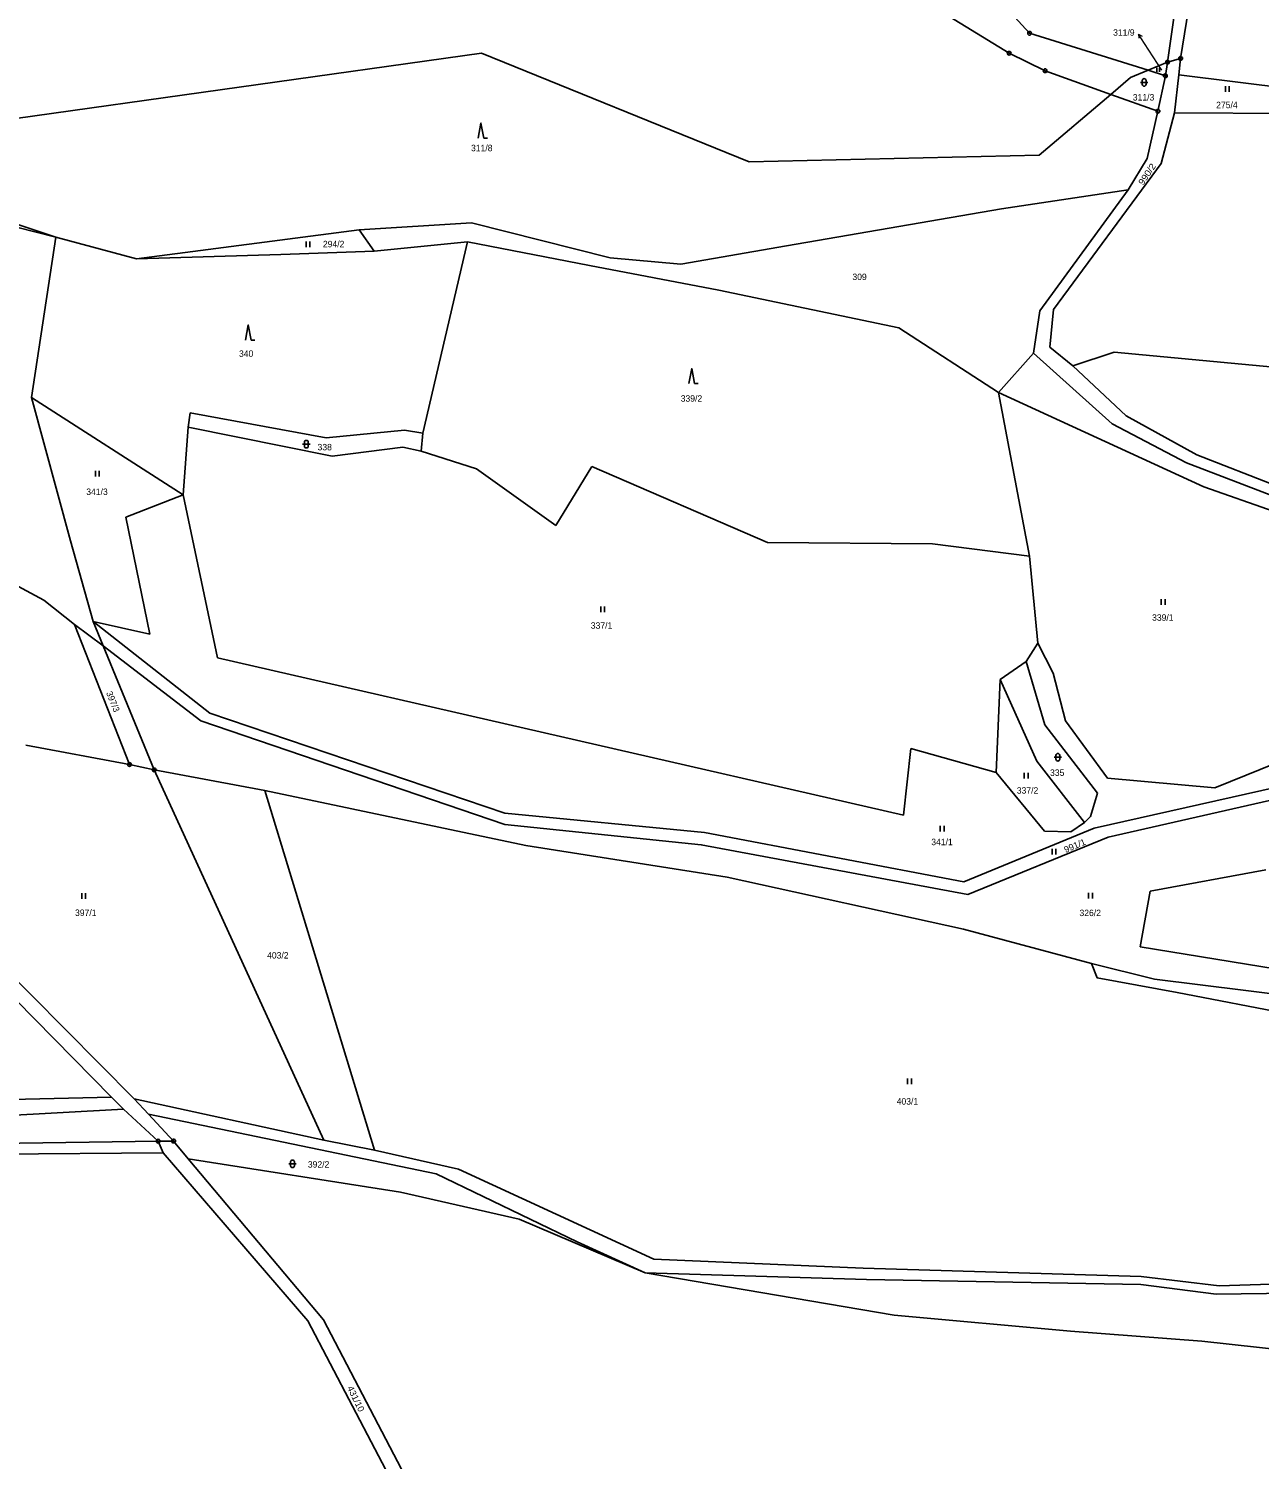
# Model space of a CAD drawing. Extents: x -754970 to -752637, y -970569 to -968179.
# Drawn here: x -753959.6 to -753633.5, y -968975.7 to -968596.7 of the extents above; entities that cross this region are included whole.
import ezdxf
from ezdxf.enums import TextEntityAlignment as Align

# ---------------------------------------------------------------- set-up
doc = ezdxf.new("R2010")
doc.units = 0
doc.header["$LTSCALE"] = 0.68
for name, color, linetype, lineweight in [('1', 7, 'Continuous', 25), ('3', 7, 'Continuous', 25), ('7', 7, 'Continuous', 13), ('8', 7, 'Continuous', 25)]:
    doc.layers.add(name, color=color, linetype=linetype, lineweight=lineweight)
doc.layers.add('2', color=7, linetype='Continuous')

msp = doc.modelspace()

# ---------------------------------------------------------------- linework, layer by layer
at = {"layer": '1'}
for p, q in [((-753718.31, -968571.75), (-753694.38, -968597.91)), ((-753657.81, -968605.58), (-753653.38, -968573.68)), ((-753650, -968577.63), (-753654.36, -968604.55)), ((-753725.93, -968587.15), (-753699.79, -968603.19)), ((-753662.97, -968607.71), (-753694.38, -968597.91)), ((-754013.82, -968627.61), (-753839.61, -968603.2)), ((-753839.61, -968603.2), (-753768.69, -968632)), ((-753699.79, -968603.19), (-753690.27, -968607.83)), ((-753672.85, -968614.08), (-753690.27, -968607.83)), ((-753662.97, -968607.71), (-753667.6, -968609.62)), ((-753657.81, -968605.58), (-753662.97, -968607.71)), ((-753662.97, -968607.71), (-753658.39, -968609.14)), ((-753658.39, -968609.14), (-753657.81, -968605.58)), ((-753654.36, -968604.55), (-753657.81, -968605.58)), ((-753654.8, -968608.94), (-753654.36, -968604.55)), ((-753667.6, -968609.62), (-753672.85, -968614.08)), ((-753658.39, -968609.14), (-753660.35, -968618.56)), ((-753655.98, -968618.97), (-753654.8, -968608.94)), ((-753609.77, -968614.45), (-753654.8, -968608.94)), ((-753672.85, -968614.08), (-753691.86, -968630.23)), ((-753672.85, -968614.08), (-753660.35, -968618.56)), ((-753663.23, -968631.09), (-753660.35, -968618.56)), ((-753659.55, -968632.43), (-753655.98, -968618.97)), ((-753622.8, -968619.16), (-753655.98, -968618.97)), ((-753691.86, -968630.23), (-753768.69, -968632)), ((-753688.02, -968671.08), (-753659.55, -968632.43)), ((-753668.24, -968639.35), (-753663.23, -968631.09)), ((-753952.37, -968651.93), (-753991.01, -968642.19)), ((-753952.37, -968651.93), (-753989.7, -968639.55)), ((-753668.24, -968639.35), (-753701.8, -968644.37)), ((-753691.7, -968671.4), (-753668.24, -968639.35)), ((-753758.78, -968654.17), (-753701.8, -968644.37)), ((-753931.05, -968657.62), (-753872.01, -968649.93)), ((-753872.01, -968649.93), (-753842.22, -968648.16)), ((-753868.08, -968655.66), (-753872.01, -968649.93)), ((-753842.22, -968648.16), (-753805.54, -968657.39)), ((-753868.08, -968655.66), (-753843.32, -968653.13)), ((-753855.16, -968703.87), (-753843.32, -968653.13)), ((-753811.03, -968659.43), (-753843.32, -968653.13)), ((-753931.05, -968657.62), (-753892.8, -968656.51)), ((-753892.8, -968656.51), (-753868.08, -968655.66)), ((-753805.54, -968657.39), (-753786.76, -968659.08)), ((-753786.76, -968659.08), (-753758.78, -968654.17)), ((-753776.71, -968665.93), (-753811.03, -968659.43)), ((-753729.05, -968675.89), (-753776.71, -968665.93)), ((-753693.31, -968682.61), (-753691.7, -968671.4)), ((-753688.98, -968681.01), (-753688.02, -968671.08)), ((-753702.59, -968693.02), (-753729.05, -968675.89)), ((-753693.31, -968682.61), (-753702.59, -968693.02)), ((-753672.46, -968701.38), (-753693.31, -968682.61)), ((-753682.9, -968685.98), (-753688.98, -968681.01)), ((-753682.9, -968685.98), (-753671.99, -968682.35)), ((-753671.99, -968682.35), (-753618.34, -968687.39)), ((-753668.81, -968699.23), (-753682.9, -968685.98)), ((-753958.87, -968694.39), (-753918.66, -968720.19)), ((-753948.48, -968732.34), (-753958.87, -968694.39)), ((-753702.59, -968693.02), (-753694.4, -968736.37)), ((-753702.59, -968693.02), (-753648.18, -968718.04)), ((-753916.83, -968698.45), (-753880.77, -968705.08)), ((-753650.07, -968709.58), (-753668.81, -968699.23)), ((-753917.35, -968702.28), (-753918.66, -968720.19)), ((-753880.77, -968705.08), (-753859.99, -968703.03)), ((-753855.16, -968703.87), (-753859.99, -968703.03)), ((-753652.8, -968711.66), (-753672.46, -968701.38)), ((-753955.63, -968748.04), (-754034.95, -968705.64)), ((-753855.64, -968708.59), (-753855.16, -968703.87)), ((-753860.47, -968707.5), (-753879.2, -968709.92)), ((-753855.64, -968708.59), (-753860.47, -968707.5)), ((-753840.91, -968713.3), (-753855.64, -968708.59)), ((-753628.81, -968717.84), (-753650.07, -968709.58)), ((-753819.89, -968728.28), (-753840.91, -968713.3)), ((-753810.35, -968712.69), (-753819.89, -968728.28)), ((-753763.85, -968732.75), (-753810.35, -968712.69)), ((-753628.61, -968720.94), (-753652.8, -968711.66)), ((-753918.66, -968720.19), (-753933.89, -968726.08)), ((-753918.66, -968720.19), (-753909.56, -968763.3)), ((-753933.89, -968726.08), (-753927.53, -968757.07)), ((-753942.55, -968753.71), (-753948.48, -968732.34)), ((-753720.13, -968733.11), (-753763.85, -968732.75)), ((-753694.4, -968736.37), (-753720.13, -968733.11)), ((-753692.23, -968759.45), (-753694.4, -968736.37)), ((-753947.46, -968754.48), (-753955.63, -968748.04)), ((-753947.46, -968754.48), (-753932.89, -968791.59)), ((-753939.86, -968760.16), (-753947.46, -968754.48)), ((-753942.55, -968753.71), (-753927.53, -968757.07)), ((-753942.55, -968753.71), (-753911.6, -968778.04)), ((-753939.86, -968760.16), (-753942.55, -968753.71)), ((-753695.25, -968764.28), (-753692.23, -968759.45)), ((-753688.12, -968767.42), (-753692.23, -968759.45)), ((-753914.01, -968780.06), (-753939.86, -968760.16)), ((-753926.33, -968793.03), (-753939.86, -968760.16)), ((-753909.56, -968763.3), (-753727.82, -968804.98)), ((-753702.13, -968769.11), (-753695.25, -968764.28)), ((-753690.3, -968781.08), (-753695.25, -968764.28)), ((-753684.86, -968779.99), (-753688.12, -968767.42)), ((-753703.24, -968793.69), (-753702.13, -968769.11)), ((-753702.13, -968769.11), (-753692.47, -968790.74)), ((-753911.6, -968778.04), (-753833.43, -968804.51)), ((-753914.01, -968780.06), (-753833.43, -968807.53)), ((-753676.41, -968799.2), (-753690.3, -968781.08)), ((-753673.73, -968795.22), (-753684.86, -968779.99)), ((-753932.89, -968791.59), (-753960.38, -968786.5)), ((-753727.82, -968804.98), (-753725.86, -968787.33)), ((-753725.86, -968787.33), (-753703.24, -968793.69)), ((-753622.35, -968788.47), (-753645.33, -968797.76)), ((-753932.89, -968791.59), (-753926.33, -968793.03)), ((-753926.33, -968793.03), (-753897.06, -968798.5)), ((-753881.38, -968891.12), (-753926.33, -968793.03)), ((-753690.41, -968809.29), (-753703.24, -968793.69)), ((-753677.28, -968808.48), (-753621.1, -968795.83)), ((-753645.33, -968797.76), (-753673.73, -968795.22)), ((-753897.06, -968798.5), (-753827.87, -968813.09)), ((-753867.94, -968893.79), (-753897.06, -968798.5)), ((-753678.22, -968805.36), (-753676.41, -968799.2)), ((-753673.56, -968810.86), (-753622.39, -968799.2)), ((-753833.43, -968804.51), (-753780.52, -968809.6)), ((-753711.8, -968822.64), (-753677.28, -968808.48)), ((-753679.79, -968806.93), (-753683.43, -968809.43)), ((-753780.52, -968809.6), (-753711.8, -968822.64)), ((-753710.71, -968826.02), (-753673.56, -968810.86)), ((-753683.43, -968809.43), (-753690.41, -968809.29)), ((-753827.87, -968813.09), (-753774.49, -968821.43)), ((-753662.4, -968825.13), (-753631.81, -968819.49)), ((-753774.49, -968821.43), (-753711.92, -968835.2)), ((-753665.08, -968839.85), (-753662.4, -968825.13)), ((-753711.92, -968835.2), (-753677.98, -968844.29)), ((-753937.67, -968879.68), (-753973.92, -968842.88)), ((-753931.61, -968880.15), (-753971.34, -968840.12)), ((-753601.44, -968850.3), (-753665.08, -968839.85)), ((-753677.98, -968844.29), (-753661.29, -968848.45)), ((-753661.29, -968848.45), (-753610.59, -968854.78)), ((-753612.25, -968860.28), (-753655.28, -968852.03)), ((-753937.67, -968879.68), (-753971.28, -968880.45)), ((-753934.48, -968882.86), (-753937.67, -968879.68)), ((-753931.61, -968880.15), (-753927.82, -968884.25)), ((-753881.38, -968891.12), (-753931.61, -968880.15)), ((-753934.48, -968882.86), (-754037.94, -968888.61)), ((-753925.26, -968891.37), (-753934.48, -968882.86)), ((-753927.82, -968884.25), (-753921.19, -968891.33)), ((-753927.82, -968884.25), (-753851.63, -968899.98)), ((-753925.26, -968891.37), (-754040.49, -968893.06)), ((-753925.26, -968891.37), (-753921.19, -968891.33)), ((-753923.94, -968894.49), (-753925.26, -968891.37)), ((-753921.19, -968891.33), (-753917.33, -968896.05)), ((-753881.38, -968891.12), (-753867.94, -968893.79)), ((-753923.94, -968894.49), (-754041.51, -968895.23)), ((-753885.65, -968938.96), (-753923.94, -968894.49)), ((-753917.33, -968896.05), (-753881.48, -968938.66)), ((-753917.33, -968896.05), (-753861.08, -968904.91)), ((-753867.94, -968893.79), (-753845.68, -968898.75)), ((-753851.63, -968899.98), (-753814.25, -968917.99)), ((-753845.68, -968898.75), (-753793.97, -968922.62)), ((-753829.59, -968912.03), (-753861.08, -968904.91)), ((-753796.21, -968926.2), (-753829.59, -968912.03)), ((-753814.25, -968917.99), (-753796.21, -968926.2)), ((-753793.97, -968922.62), (-753738.49, -968925.05)), ((-753796.21, -968926.2), (-753737.58, -968928.03)), ((-753796.21, -968926.2), (-753730.29, -968937.45)), ((-753738.49, -968925.05), (-753664.8, -968927.24)), ((-753737.58, -968928.03), (-753664.92, -968929.37)), ((-753664.92, -968929.37), (-753644.94, -968931.92)), ((-753664.8, -968927.24), (-753644.15, -968929.67)), ((-753644.15, -968929.67), (-753619.67, -968928.94)), ((-753644.94, -968931.92), (-753620.22, -968931.55)), ((-753730.29, -968937.45), (-753683.51, -968941.71)), ((-753885.65, -968938.96), (-753853.84, -968999.51)), ((-753881.48, -968938.66), (-753850.68, -968997.64)), ((-753683.51, -968941.71), (-753648.7, -968944.32)), ((-753648.7, -968944.32), (-753625.45, -968946.87))]:
    msp.add_line(p, q, dxfattribs=at)
for points in [[(-753958.87, -968694.39), (-753952.37, -968651.93), (-753931.05, -968657.62)], [(-753879.2, -968709.92), (-753917.35, -968702.28), (-753916.83, -968698.45)], [(-753648.18, -968718.04), (-753629.58, -968724.59), (-753599.11, -968734.07)], [(-753692.47, -968790.74), (-753679.79, -968806.93), (-753678.22, -968805.36)], [(-753833.43, -968807.53), (-753781.37, -968812.86), (-753710.71, -968826.02)], [(-753655.28, -968852.03), (-753676.45, -968848.13), (-753677.98, -968844.29)]]:
    msp.add_lwpolyline(points, dxfattribs=at)
at = {"layer": '3'}
for p, q in [((-753660.642, -968608.09), (-753660.642, -968607.085)), ((-753659.972, -968608.09), (-753659.972, -968607.085)), ((-753665.001, -968610.921), (-753662.999, -968610.921)), ((-753664.501, -968610.421), (-753664.501, -968611.422)), ((-753663.499, -968611.422), (-753663.499, -968610.421)), ((-753642.481, -968613.44), (-753642.481, -968611.94)), ((-753641.48, -968613.44), (-753641.48, -968611.94)), ((-753839, -968625.69), (-753838.004, -968625.69)), ((-753886.061, -968654.6), (-753886.061, -968653.1)), ((-753885.06, -968654.6), (-753885.06, -968653.1)), ((-753900.67, -968679.17), (-753899.674, -968679.17)), ((-753783.17, -968690.71), (-753782.174, -968690.71)), ((-753887.031, -968706.731), (-753885.029, -968706.731)), ((-753886.531, -968706.231), (-753886.531, -968707.232)), ((-753885.529, -968707.232), (-753885.529, -968706.231)), ((-753941.911, -968715.27), (-753941.911, -968713.77)), ((-753940.91, -968715.27), (-753940.91, -968713.77)), ((-753659.481, -968749.26), (-753659.481, -968747.76)), ((-753658.48, -968749.26), (-753658.48, -968747.76)), ((-753808.021, -968751.23), (-753808.021, -968749.73)), ((-753807.02, -968751.23), (-753807.02, -968749.73)), ((-753687.881, -968789.671), (-753685.879, -968789.671)), ((-753687.381, -968789.171), (-753687.381, -968790.172)), ((-753686.379, -968790.172), (-753686.379, -968789.171)), ((-753695.771, -968795.28), (-753695.771, -968793.78)), ((-753694.77, -968795.28), (-753694.77, -968793.78)), ((-753718.051, -968809.33), (-753718.051, -968807.83)), ((-753717.05, -968809.33), (-753717.05, -968807.83)), ((-753688.391, -968815.47), (-753688.391, -968813.97)), ((-753687.39, -968815.47), (-753687.39, -968813.97)), ((-753945.511, -968827.18), (-753945.511, -968825.68)), ((-753944.51, -968827.18), (-753944.51, -968825.68)), ((-753678.721, -968827.07), (-753678.721, -968825.57)), ((-753677.72, -968827.07), (-753677.72, -968825.57)), ((-753726.701, -968876.25), (-753726.701, -968874.75)), ((-753725.7, -968876.25), (-753725.7, -968874.75)), ((-753890.691, -968897.361), (-753888.689, -968897.361)), ((-753890.191, -968896.861), (-753890.191, -968897.862)), ((-753889.189, -968897.862), (-753889.189, -968896.861))]:
    msp.add_line(p, q, dxfattribs=at)
for points in [[(-753839, -968625.69), (-753839.75, -968621.69), (-753840.5, -968625.69)], [(-753900.67, -968679.17), (-753901.42, -968675.17), (-753902.17, -968679.17)], [(-753783.17, -968690.71), (-753783.92, -968686.71), (-753784.67, -968690.71)]]:
    msp.add_lwpolyline(points, dxfattribs=at)
for centre, start, end in [((-753664, -968610.4209), 0, 180), ((-753664, -968611.4209), 180, 359.98789), ((-753886.03, -968706.2309), 0, 180), ((-753886.03, -968707.2309), 180, 359.98789), ((-753686.88, -968789.1709), 0, 180), ((-753686.88, -968790.1709), 180, 359.98789), ((-753889.69, -968896.8609), 0, 180), ((-753889.69, -968897.8609), 180, 359.98789)]:
    msp.add_arc(centre, 0.5, start, end, dxfattribs=at)
at = {"layer": '7'}
msp.add_line((-753665.544, -968598.123), (-753665.419, -968599.236), dxfattribs=at)
msp.add_lwpolyline([(-753659.34, -968607.66), (-753663.91, -968600.64), (-753665.544, -968598.123), (-753664.579, -968598.69)], dxfattribs=at)
at = {"layer": '8'}
for centre, radius in [((-753694.38, -968597.9099), 0.5), ((-753694.38, -968597.9099), 0.0303), ((-753699.79, -968603.1899), 0.5), ((-753699.79, -968603.1899), 0.0303), ((-753654.36, -968604.5499), 0.5), ((-753690.27, -968607.8299), 0.5), ((-753690.27, -968607.8299), 0.0303), ((-753657.81, -968605.5799), 0.5), ((-753657.81, -968605.5799), 0.0303), ((-753654.36, -968604.5499), 0.0303), ((-753658.39, -968609.1399), 0.5), ((-753658.39, -968609.1399), 0.0303), ((-753660.35, -968618.5599), 0.5), ((-753660.35, -968618.5599), 0.0303), ((-753932.89, -968791.5899), 0.5), ((-753932.89, -968791.5899), 0.0303), ((-753926.33, -968793.0299), 0.5), ((-753926.33, -968793.0299), 0.0303), ((-753925.26, -968891.3699), 0.5), ((-753925.26, -968891.3699), 0.0303), ((-753921.19, -968891.3299), 0.5), ((-753921.19, -968891.3299), 0.0303)]:
    msp.add_circle(centre, radius, dxfattribs=at)

# ---------------------------------------------------------------- texts
at = {"layer": '2'}
msp.add_text('311/9', height=1.7, dxfattribs=at).set_placement((-753666.55, -968598.555), align=Align.RIGHT)
for s, p in [('311/3', (-753664.18, -968615.715)), ('275/4', (-753642.09, -968617.755)), ('311/8', (-753839.54, -968629.145)), ('294/2', (-753878.79, -968654.585)), ('309', (-753739.429, -968663.275)), ('340', (-753901.969, -968683.615)), ('339/2', (-753783.98, -968695.485)), ('338', (-753881.159, -968708.375)), ('341/3', (-753941.5, -968720.195)), ('339/1', (-753659.07, -968753.525)), ('337/1', (-753807.8, -968755.635)), ('335', (-753687.059, -968794.605)), ('337/2', (-753694.92, -968799.315)), ('341/1', (-753717.58, -968812.965)), ('397/1', (-753944.48, -968831.705)), ('326/2', (-753678.31, -968831.755)), ('403/2', (-753893.58, -968842.985)), ('403/1', (-753726.75, -968881.675)), ('392/2', (-753882.78, -968898.375))]:
    msp.add_text(s, height=1.7, dxfattribs=at).set_placement(p, align=Align.CENTER)
for s, rotation, width, p in [('990/2', 56, 1.1, (-753662.5439, -968635.7048)), ('991/1', 23, 1.05, (-753682.0641, -968813.889)), ('431/10', 296, 1.05, (-753873.6689, -968959.9854))]:
    msp.add_text(s, height=1.7, rotation=rotation, dxfattribs=dict(at, width=width)).set_placement(p, align=Align.CENTER)
msp.add_text('397/3', height=1.7, rotation=292, dxfattribs=at).set_placement((-753938.0481, -968775.2506), align=Align.CENTER)

doc.saveas('drawing.dxf')
